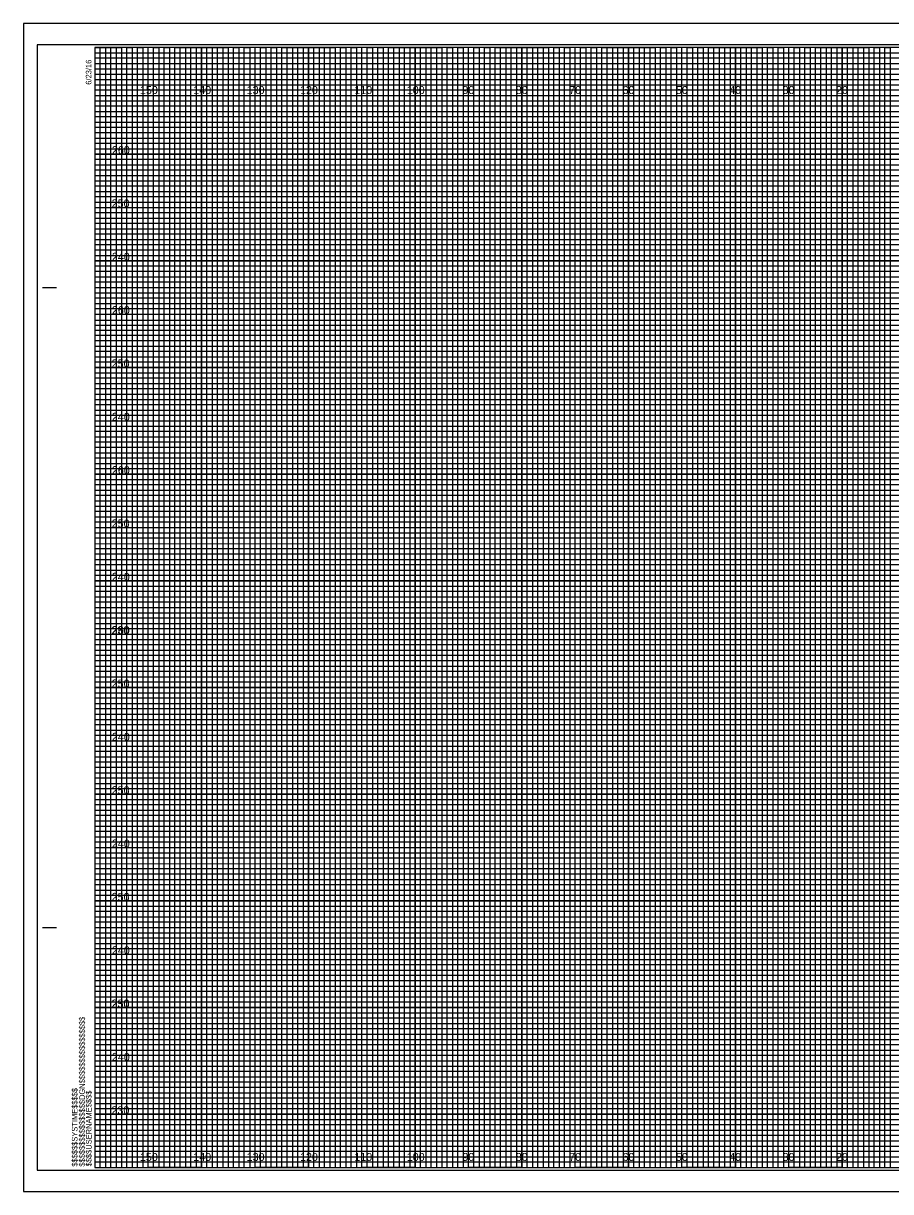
# Model space of a CAD drawing. Extents: x -13 to 359, y -5 to 2854.
# Drawn here: x -13.4 to 149.1, y 1975.5 to 2194.5 of the extents above; entities that cross this region are included whole.
import ezdxf

# ---------------------------------------------------------------- set-up
doc = ezdxf.new("R2010")
doc.units = 0
for name, color, linetype in [('Exist Cross Section Cell', 7, 'Continuous'), ('Exist XS Ground Line', 7, 'Continuous'), ('Prop CMT Concrete Structures', 7, 'Continuous'), ('Prop CMT DNC', 7, 'Continuous'), ('Prop CMT Pvmt Course 1', 7, 'Continuous'), ('Prop CMT Pvmt Course 1 CG', 7, 'Continuous'), ('Prop CMT Pvmt Course 2', 7, 'Continuous'), ('Prop CMT Shear Line', 7, 'Continuous'), ('Prop CMT Slope Grass', 7, 'Continuous'), ('Prop CMT Subgrade Earthwork', 7, 'Continuous'), ('Scratch_Level_0', 7, 'Continuous')]:
    doc.layers.add(name, color=color, linetype=linetype)

msp = doc.modelspace()

# ---------------------------------------------------------------- linework, layer by layer
at = {"layer": 'Exist XS Ground Line'}
for p, q in [((10, 2190), (0, 2190)), ((10, 1980), (10, 2190)), ((30, 2190), (20, 2190)), ((20, 2190), (20, 1980)), ((30, 1980), (30, 2190)), ((50, 2190), (40, 2190)), ((40, 2190), (40, 1980)), ((50, 1980), (50, 2190)), ((70, 2190), (60, 2190)), ((60, 2190), (60, 1980)), ((70, 1980), (70, 2190)), ((90, 2190), (80, 2190)), ((80, 2190), (80, 1980)), ((90, 1980), (90, 2190)), ((110, 2190), (100, 2190)), ((100, 2190), (100, 1980)), ((110, 1980), (110, 2190)), ((130, 2190), (120, 2190)), ((120, 2190), (120, 1980)), ((130, 1980), (130, 2190)), ((150, 2190), (140, 2190)), ((140, 2190), (140, 1980)), ((20, 1980), (10, 1980)), ((40, 1980), (30, 1980)), ((60, 1980), (50, 1980)), ((80, 1980), (70, 1980)), ((100, 1980), (90, 1980)), ((120, 1980), (110, 1980)), ((140, 1980), (130, 1980))]:
    msp.add_line(p, q, dxfattribs=at)
for points in [[(0, 2180), (320, 2180), (320, 2170), (0, 2170)], [(0, 2160), (320, 2160), (320, 2150), (0, 2150)], [(0, 2140), (320, 2140), (320, 2130), (0, 2130)], [(0, 2120), (320, 2120), (320, 2110), (0, 2110)], [(0, 2100), (320, 2100), (320, 2090), (0, 2090)], [(0, 2080), (320, 2080), (320, 2070), (0, 2070)], [(0, 2060), (320, 2060), (320, 2050), (0, 2050)], [(0, 2040), (320, 2040), (320, 2030), (0, 2030)], [(0, 2020), (320, 2020), (320, 2010), (0, 2010)], [(0, 2000), (320, 2000), (320, 1990), (0, 1990)]]:
    msp.add_lwpolyline(points, dxfattribs=at)
at = {"layer": 'Prop CMT Concrete Structures'}
for p, q in [((-9.8, 2145), (-7.3, 2145)), ((-9.7, 2145), (-7.2, 2145)), ((-9.8, 2025), (-7.3, 2025)), ((-9.7, 2025), (-7.2, 2025)), ((0, 1980), (0, 1980)), ((0, 1980), (0, 1980)), ((0, 1980), (0, 1980)), ((0, 1980), (0, 1980)), ((0, 1980), (0, 1980)), ((0, 1980), (0, 1980)), ((0, 1980), (0, 1980))]:
    msp.add_line(p, q, dxfattribs=at)
msp.add_lwpolyline([(320, 2190), (0, 2190), (0, 1980), (320, 1980)], close=True, dxfattribs=at)
at = {"layer": 'Prop CMT DNC'}
for p, q in [((323.3, 2194.5), (-13.4, 2194.5)), ((-13.4, 2194.5), (-13.4, 1975.5)), ((-13.4, 1975.5), (323.3, 1975.5))]:
    msp.add_line(p, q, dxfattribs=at)
at = {"layer": 'Prop CMT Pvmt Course 1'}
for p, q in [((0, 2189), (260, 2189)), ((260, 2187.98), (0, 2187.98)), ((0, 2187.98), (0, 2187)), ((0, 2187), (260, 2187)), ((260, 2185.89), (0, 2185.89)), ((0, 2185.89), (0, 2184)), ((0, 2184), (320, 2184))]:
    msp.add_line(p, q, dxfattribs=at)
for points in [[(0, 2183), (270, 2183), (320, 2183), (320, 2182), (0, 2182)], [(0, 2181), (320, 2181), (320, 2179), (0, 2179)], [(0, 2178), (320, 2178), (320, 2177), (0, 2176.98)], [(0, 2176), (320, 2176), (320, 2174), (0, 2174)], [(0, 2173), (320, 2173), (320, 2172), (0, 2172)], [(0, 2171), (320, 2171), (320, 2169), (0, 2169)], [(0, 2168), (320, 2168), (320, 2167), (0, 2167)], [(0, 2166), (320, 2166), (320, 2164), (0, 2164)], [(0, 2163), (320, 2163), (320, 2162), (0, 2162)], [(0, 2161), (320, 2161), (320, 2159), (0, 2159)], [(0, 2158), (320, 2158), (320, 2157), (0, 2157)], [(0, 2156), (320, 2156), (320, 2153.95), (320, 2153), (320, 2152), (0, 2152)], [(0, 2154), (320, 2154), (320, 2153), (0, 2153)], [(0, 2151), (320, 2151), (320, 2149), (0, 2149.03)], [(0, 2149.03), (320, 2149), (320, 2148), (0, 2148)], [(0, 2147), (320, 2147), (320, 2146), (0, 2146)], [(0, 2144), (320, 2144), (320, 2143), (0, 2143)], [(0, 2142), (320, 2142), (320, 2141), (0, 2141)], [(-0.07, 2138.89), (320, 2138.89), (320, 2137.88), (-0.07, 2137.88)], [(0, 2137), (320, 2137), (320, 2136), (0, 2136)], [(0, 2134), (320, 2134), (320, 2133), (0, 2133)], [(0, 2132), (320, 2132), (320, 2131), (0, 2131)], [(0, 2129), (320, 2129), (320, 2128), (0, 2128)], [(0, 2127), (320, 2127), (320, 2126), (0, 2126)], [(0, 2124), (320, 2124), (320, 2123), (0, 2123)], [(0, 2122), (320, 2122), (320, 2121), (0, 2121)], [(0, 2119), (320, 2119), (319.99, 2117.98), (0, 2118)], [(0, 2117), (320, 2117), (320, 2116), (0, 2116)], [(0, 2114), (320, 2114), (320, 2113), (0, 2113)], [(0, 2112), (320, 2112), (320, 2111), (0, 2111)], [(0, 2109), (320, 2109), (320, 2108), (0, 2108)], [(0, 2107), (320, 2107), (320, 2106), (0, 2106)], [(0, 2104), (320, 2104), (320, 2103), (0, 2103)], [(0, 2102), (320, 2102), (320, 2101), (0, 2101)], [(0, 2099), (320, 2099), (320, 2098), (0, 2098)], [(0, 2096.99), (320.07, 2096.91), (320, 2096), (0, 2096)], [(0, 2094), (320, 2094), (320, 2093), (0, 2093)], [(0, 2092), (320, 2092), (320, 2091), (0, 2091)], [(0, 2089), (320, 2089), (320, 2088), (0, 2088)], [(0, 2087), (320, 2087), (320, 2086), (0, 2086)], [(0, 2084), (320, 2084), (320, 2083), (0, 2083)], [(0, 2082), (320, 2082), (320, 2081), (0, 2081)], [(0, 2079), (320, 2079), (320, 2078), (0, 2078)], [(0, 2077), (320, 2077), (320, 2076), (0, 2076)], [(0, 2074), (320, 2074), (320, 2073), (0, 2073)], [(0, 2072), (320, 2072), (320, 2071), (0, 2071)], [(0, 2069), (320, 2069), (320, 2068), (0, 2068)], [(0, 2067), (320, 2067), (320, 2066), (0, 2066)], [(0, 2064), (320, 2064), (320, 2063), (0, 2063)], [(0, 2062), (320, 2062), (320, 2061), (0, 2061)], [(0, 2059), (320, 2059), (319.99, 2057.98), (0, 2058)], [(0, 2057), (320, 2057), (320, 2056), (0, 2056)], [(0, 2054), (320, 2054), (320, 2053), (0, 2053)], [(0, 2052), (320, 2052), (320, 2051), (0, 2051)], [(0, 2049), (320, 2049), (320, 2048), (0, 2048)], [(0, 2047), (320, 2047), (320, 2046), (0, 2046)], [(0, 2044), (320, 2044), (320, 2043), (0, 2043)], [(0, 2042), (320, 2042), (320, 2041), (0, 2041)], [(0, 2039), (320, 2039), (320, 2038), (0, 2038)], [(0, 2036.99), (320.07, 2036.91), (320, 2036), (0, 2036)], [(0, 2034), (320, 2034), (320, 2033), (0, 2033)], [(0, 2032), (320, 2032), (320, 2031), (0, 2031)], [(0, 2029), (320, 2029), (320, 2028), (0, 2028)], [(0, 2027), (320, 2027), (320, 2026), (0, 2026)], [(0, 2024), (320, 2024), (320, 2023), (0, 2023)], [(0, 2022), (320, 2022), (320, 2021), (0, 2021)], [(0, 2019), (320, 2019), (320, 2018), (0, 2018)], [(0, 2017), (320, 2017), (320, 2016), (0, 2016)], [(0, 2014), (320, 2014), (320, 2013), (0, 2013)], [(0, 2012), (320, 2012), (320, 2011), (0, 2011)], [(0, 2009), (320, 2009), (320, 2008), (0, 2008)], [(0, 2007), (320, 2007), (320, 2006), (0, 2006)], [(0, 2004), (320, 2004), (320, 2003), (0, 2003)], [(0, 2002), (320, 2002), (320, 2001), (0, 2001)], [(0, 1999), (320, 1999), (320, 1998), (0, 1998)], [(0, 1997), (320, 1997), (320, 1996), (0, 1996)], [(0, 1994), (320, 1994), (320, 1993), (0, 1993)], [(0, 1992), (320, 1992), (320, 1991), (0, 1991)], [(0, 1989), (320, 1989), (320, 1988), (0, 1988)], [(0, 1987), (320, 1987), (320, 1986), (0, 1986)], [(0, 1984), (320, 1984), (320, 1983), (0, 1983)], [(0, 1982), (320, 1982), (320, 1981), (0, 1981)]]:
    msp.add_lwpolyline(points, dxfattribs=at)
at = {"layer": 'Prop CMT Pvmt Course 1 CG'}
for points in [[(0, 1980), (1, 1980), (1, 2190), (2, 2190), (2, 1980)], [(2, 1980), (3, 1980), (3, 2190), (4, 2190), (4, 1980)], [(5, 1980), (6, 1980), (6, 2190), (7, 2190), (7, 1980)], [(7, 1980), (8, 1980), (8, 2190), (9, 2190), (9, 1980)], [(10, 1980), (11, 1980), (11, 2190), (12, 2190), (12, 1980)], [(12, 1980), (13, 1980), (13, 2190), (14, 2190), (14, 1980)], [(15, 1980), (16, 1980), (16, 2190), (17, 2190), (17, 1980)], [(17, 1980), (18, 1980), (18, 2190), (19, 2190), (19, 1980)], [(20, 1980), (21, 1980), (21, 2190), (22, 2190), (22, 1980)], [(22, 1980), (23, 1980), (23, 2190), (24, 2190), (24, 1980)], [(25, 1980), (26, 1980), (26, 2190), (27, 2190), (27, 1980)], [(27, 1980), (28, 1980), (28, 2190), (29, 2190), (29, 1980)], [(30, 1980), (31, 1980), (31, 2190), (32, 2190), (32, 1980)], [(32, 1980), (33, 1980), (33, 2190), (34, 2190), (34, 1980)], [(35, 1980), (36, 1980), (36, 2190), (37, 2190), (37, 1980)], [(37, 1980), (38, 1980), (38, 2190), (39, 2190), (39, 1980)], [(40, 1980), (41, 1980), (41, 2190), (42, 2190), (42, 1980)], [(42, 1980), (43, 1980), (43, 2190), (44, 2190), (44, 1980)], [(45, 1980), (46, 1980), (46, 2190), (47, 2190), (47, 1980)], [(47, 1980), (48, 1980), (48, 2190), (49, 2190), (49, 1980)], [(50, 1980), (51, 1980), (51, 2190), (52, 2190), (52, 1980)], [(52, 1980), (53, 1980), (53, 2190), (54, 2190), (54, 1980)], [(55, 1980), (56, 1980), (56, 2190), (57, 2190), (57, 1980)], [(57, 1980), (58, 1980), (58, 2190), (59, 2190), (59, 1980)], [(60, 1980), (61, 1980), (61, 2190), (62, 2190), (62, 1980)], [(62, 1980), (63, 1980), (63, 2190), (64, 2190), (64, 1980)], [(65, 1980), (66, 1980), (66, 2190), (67, 2190), (67, 1980)], [(67, 1980), (68, 1980), (68, 2190), (69, 2190), (69, 1980)], [(70, 1980), (71, 1980), (71, 2190), (72, 2190), (72, 1980)], [(72, 1980), (73, 1980), (73, 2190), (74, 2190), (74, 1980)], [(75, 1980), (76, 1980), (76, 2190), (77, 2190), (77, 1980)], [(77, 1980), (78, 1980), (78, 2190), (79, 2190), (79, 1980)], [(80, 1980), (81, 1980), (81, 2190), (82, 2190), (82, 1980)], [(82, 1980), (83, 1980), (83, 2190), (84, 2190), (84, 1980)], [(85, 1980), (86, 1980), (86, 2190), (87, 2190), (87, 1980)], [(87, 1980), (88, 1980), (88, 2190), (89, 2190), (89, 1980)], [(90, 1980), (91, 1980), (91, 2190), (92, 2190), (92, 1980)], [(92, 1980), (93, 1980), (93, 2190), (94, 2190), (94, 1980)], [(95, 1980), (96, 1980), (96, 2190), (97, 2190), (97, 1980)], [(97, 1980), (98, 1980), (98, 2190), (99, 2190), (99, 1980)], [(100, 1980), (101, 1980), (101, 2190), (102, 2190), (102, 1980)], [(102, 1980), (103, 1980), (103, 2190), (104, 2190), (104, 1980)], [(105, 1980), (106, 1980), (106, 2190), (107, 2190), (107, 1980)], [(107, 1980), (108, 1980), (108, 2190), (109, 2190), (109, 1980)], [(110, 1980), (111, 1980), (111, 2190), (112, 2190), (112, 1980)], [(112, 1980), (113, 1980), (113, 2190), (114, 2190), (114, 1980)], [(115, 1980), (116, 1980), (116, 2190), (117, 2190), (117, 1980)], [(117, 1980), (118, 1980), (118, 2190), (119, 2190), (119, 1980)], [(120, 1980), (121, 1980), (121, 2190), (122, 2190), (122, 1980)], [(122, 1980), (123, 1980), (123, 2190), (124, 2190), (124, 1980)], [(125, 1980), (126, 1980), (126, 2190), (127, 2190), (127, 1980)], [(127, 1980), (128, 1980), (128, 2190), (129, 2190), (129, 1980)], [(130, 1980), (131, 1980), (131, 2190), (132, 2190), (132, 1980)], [(132, 1980), (133, 1980), (133, 2190), (134, 2190), (134, 1980)], [(135, 1980), (136, 1980), (136, 2190), (137, 2190), (137, 1980)], [(137, 1980), (138, 1980), (138, 2190), (139, 2190), (139, 1980)], [(140, 1980), (141, 1980), (141, 2190), (142, 2190), (142, 1980)], [(142, 1980), (143, 1980), (143, 2190), (144, 2190), (144, 1980)], [(145, 1980), (146, 1980), (146, 2190), (147, 2190), (147, 1980)], [(147, 1980), (148, 1980), (148, 2190), (149, 2190), (149, 1980)]]:
    msp.add_lwpolyline(points, dxfattribs=at)
at = {"layer": 'Prop CMT Shear Line'}
for p, q in [((10, 1980), (10, 2190)), ((20, 1980), (20, 2190)), ((30, 1980), (30, 2190)), ((40, 1980), (40, 2190)), ((50, 1980), (50, 2190)), ((60, 1980), (60, 2190)), ((70, 1980), (70, 2190)), ((80, 1980), (80, 2190)), ((90, 1980), (90, 2190)), ((100, 1980), (100, 2190)), ((110, 1980), (110, 2190)), ((120, 1980), (120, 2190)), ((130, 1980), (130, 2190)), ((140, 1980), (140, 2190)), ((0, 2180), (320, 2180)), ((0, 2170), (320, 2170)), ((0, 2160), (320, 2160)), ((0, 2150), (320, 2150)), ((0, 2140), (320, 2140)), ((0, 2130), (320, 2130)), ((0, 2120), (320, 2120)), ((0, 2110), (320, 2110)), ((0, 2100), (320, 2100)), ((0, 2090), (320, 2090)), ((0, 2080), (320, 2080)), ((0, 2070), (320, 2070)), ((0, 2060), (320, 2060)), ((0, 2050), (320, 2050)), ((0, 2040), (320, 2040)), ((0, 2030), (320, 2030)), ((0, 2020), (320, 2020)), ((0, 2010), (320, 2010)), ((0, 2000), (320, 2000)), ((0, 1990), (320, 1990))]:
    msp.add_line(p, q, dxfattribs=at)
at = {"layer": 'Prop CMT Slope Grass'}
msp.add_lwpolyline([(-10.8, 1979.5), (322.4, 1979.5), (322.4, 2190.5), (-10.8, 2190.5)], close=True, dxfattribs=at)
at = {"layer": 'Prop CMT Subgrade Earthwork'}
msp.add_lwpolyline([(-13.4, 1975.5), (323.3, 1975.5), (323.3, 2194.5), (-13.4, 2194.5)], close=True, dxfattribs=at)
at = {"layer": 'Scratch_Level_0'}
for points in [[(0, 2190), (5, 2190), (5, 1980), (15, 1980), (15, 2190), (25, 2190), (25, 1980), (35, 1980), (35, 2190), (45, 2190), (45, 1980), (55, 1980), (55, 2190), (65, 2190), (65, 1980), (75, 1980), (75, 2190), (85, 2190), (85, 1980), (95, 1980), (95, 2190), (105, 2190), (105, 1980), (115, 1980), (115, 2190), (125, 2190), (125, 1980), (135, 1980), (135, 2190), (145, 2190), (145, 1980), (155, 1980)], [(0, 2185), (275, 2185)], [(0, 2165), (320, 2165), (320, 2175), (0, 2175)], [(0, 2145), (320, 2145), (320, 2155), (0, 2155)], [(0, 2125), (320, 2125), (320, 2135), (0, 2135)], [(0, 2105), (320, 2105), (320, 2115), (0, 2115)], [(0, 2085), (320, 2085), (320, 2095), (0, 2095)], [(0, 2065), (320, 2065), (320, 2075), (0, 2075)], [(0, 2045), (320, 2045), (320, 2055), (0, 2055)], [(0, 2025), (320, 2025), (320, 2035), (0, 2035)], [(0, 2005), (320, 2005), (320, 2015), (0, 2015)], [(0, 1985), (320, 1985), (320, 1995), (0, 1995)]]:
    msp.add_lwpolyline(points, dxfattribs=at)

# ---------------------------------------------------------------- texts
at = {"layer": 'Exist Cross Section Cell'}
for s, p in [('150', (8.44, 2181.25)), ('140', (18.44, 2181.25)), ('130', (28.44, 2181.25)), ('120', (38.44, 2181.25)), ('110', (48.62, 2181.25)), ('100', (58.44, 2181.25)), ('90', (68.86, 2181.25)), ('80', (78.86, 2181.25)), ('70', (88.86, 2181.25)), ('60', (98.86, 2181.25)), ('50', (108.86, 2181.25)), ('40', (118.86, 2181.25)), ('30', (128.86, 2181.25)), ('20', (138.86, 2181.25)), ('150', (8.44, 1981.25)), ('140', (18.44, 1981.25)), ('130', (28.44, 1981.25)), ('120', (38.44, 1981.25)), ('110', (48.62, 1981.25)), ('100', (58.44, 1981.25)), ('90', (68.86, 1981.25)), ('80', (78.86, 1981.25)), ('70', (88.86, 1981.25)), ('60', (98.86, 1981.25)), ('50', (108.86, 1981.25)), ('40', (118.86, 1981.25)), ('30', (128.86, 1981.25)), ('20', (138.86, 1981.25))]:
    msp.add_text(s, height=1.5, dxfattribs=at).set_placement(p)
at = {"layer": 'Prop CMT Concrete Structures'}
for s, p in [('6/23/16', (-0.65, 2183)), ('$$$$$$$$$$$$$$$$DGN$$$$$$$$$$$$$$$$', (-1.88, 1980.18)), ('$$$$$$SYSTIME$$$$$', (-3.26, 1980.18)), ('$$$$USERNAME$$$$', (-0.62, 1980.23))]:
    msp.add_text(s, height=1.05, rotation=90, dxfattribs=at).set_placement(p)
at = {"layer": 'Prop CMT Pvmt Course 2'}
for s, p in [('260', (3.19, 2170)), ('250', (3.15, 2160)), ('240', (3.19, 2150)), ('260', (3.19, 2140)), ('250', (3.15, 2130)), ('240', (3.19, 2120)), ('260', (3.19, 2110)), ('250', (3.15, 2100)), ('240', (3.19, 2090)), ('230', (3.11, 2080)), ('260', (3.19, 2080)), ('250', (3.15, 2070)), ('240', (3.19, 2060)), ('250', (3.15, 2050)), ('240', (3.19, 2040)), ('250', (3.15, 2030)), ('240', (3.19, 2020)), ('230', (3.11, 2010)), ('250', (3.15, 2010)), ('240', (3.19, 2000)), ('230', (3.11, 1990))]:
    msp.add_text(s, height=1.5, dxfattribs=at).set_placement(p)

doc.saveas('drawing.dxf')
